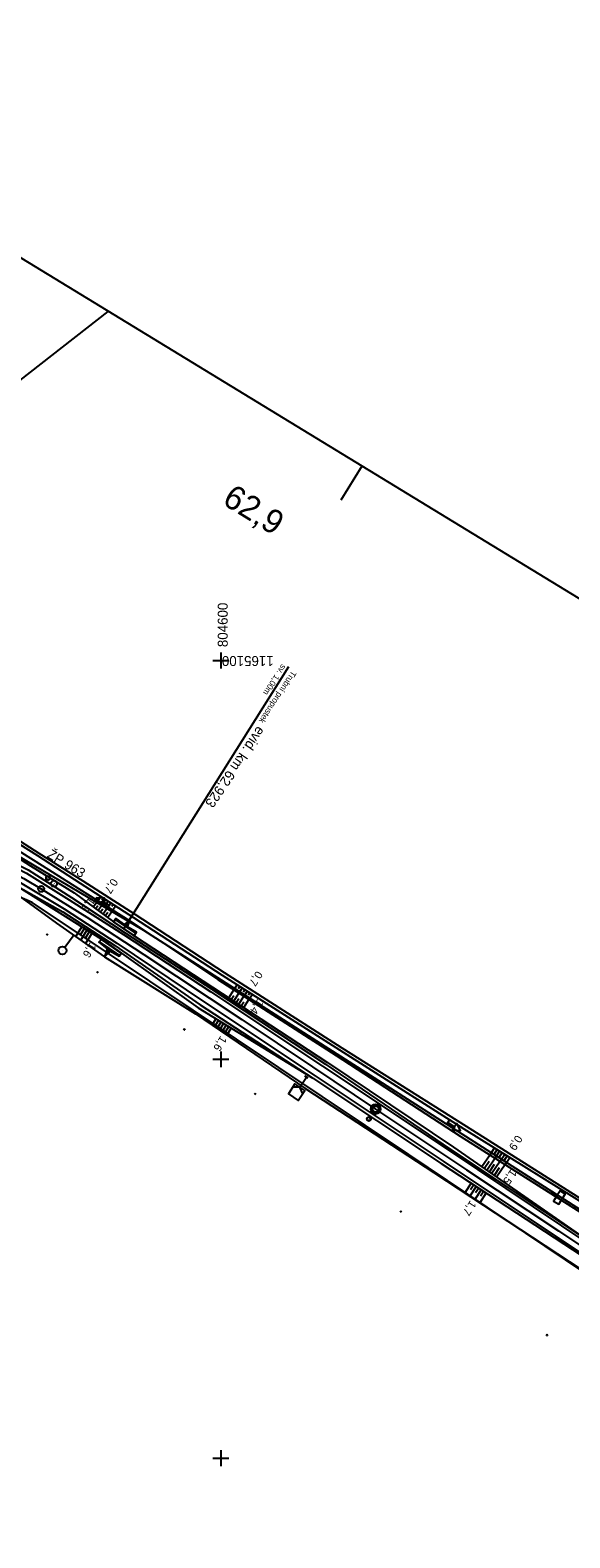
# Model space of a CAD drawing. Extents: x -804899 to -803847, y -1165742 to -1164942.
# Drawn here: x -804647.9 to -804512.4, y -1165320 to -1164941.9 of the extents above; entities that cross this region are included whole.
import ezdxf

# ---------------------------------------------------------------- set-up
doc = ezdxf.new("R2010")
doc.units = 0
for name, color, linetype in [('0381KM061-064P - Vrstva 1', 7, 'Continuous'), ('0381KM061-064P - Vrstva 17', 7, 'Continuous'), ('0381KM061-064P - Vrstva 19', 7, 'Continuous'), ('0381KM061-064P - Vrstva 36', 7, 'Continuous'), ('0381KM061-064P - Vrstva 4', 7, 'Continuous'), ('0381KM061-064P - Vrstva 48', 7, 'Continuous'), ('0381KM061-064P - Vrstva 49', 7, 'Continuous'), ('0381KM061-064P - Vrstva 51', 7, 'Continuous'), ('0381KM061-064P - Vrstva 55', 7, 'Continuous'), ('0381KM061-064P - Vrstva 7', 7, 'Continuous'), ('formát', 7, 'Continuous'), ('hran DP - hran DP', 7, 'Continuous'), ('krizky_1000 - souradnice', 7, 'Continuous'), ('krizky_1000 - Vrstva 1', 7, 'Continuous'), ('vyt_sit - stávající', 7, 'Continuous')]:
    doc.layers.add(name, color=color, linetype=linetype)

msp = doc.modelspace()

# ---------------------------------------------------------------- linework, layer by layer
at = {"layer": '0381KM061-064P - Vrstva 1'}
for points in [[(-804666.44, -1165145.5), (-804649.48, -1165154.65), (-804645.14, -1165157.27), (-804633.7, -1165164.38), (-804619.36, -1165173.74)], [(-804619.36, -1165173.74), (-804594.78, -1165190.05), (-804577, -1165201.91), (-804561.16, -1165212.47), (-804538.32, -1165227.67), (-804515.3, -1165243.02), (-804489.41, -1165260.27), (-804477.81, -1165268), (-804447.6, -1165288.14), (-804422.03, -1165305.2), (-804398.19, -1165321.09), (-804394.23, -1165323.73), (-804371.85, -1165338.65), (-804349.9, -1165353.29), (-804326.64, -1165368.8), (-804303.84, -1165384.01), (-804280.33, -1165399.7), (-804257.04, -1165415.23), (-804233.85, -1165430.69)]]:
    msp.add_lwpolyline(points, dxfattribs=at)
at = {"layer": '0381KM061-064P - Vrstva 17'}
for p, q in [((-804621.51, -1165168.31), (-804626.41, -1165164.99)), ((-804625.42, -1165173.99), (-804630.34, -1165170.65))]:
    msp.add_line(p, q, dxfattribs=at)
at = {"layer": '0381KM061-064P - Vrstva 19'}
msp.add_line((-804624.36, -1165167.24), (-804582.93, -1165101.49), dxfattribs=at)
for points in [[(-804626.92, -1165165.53), (-804626.96, -1165165.56), (-804626.42, -1165164.7), (-804626.38, -1165164.82)], [(-804621.79, -1165169), (-804626.96, -1165165.56)], [(-804621.8, -1165168.94), (-804626.92, -1165165.53), (-804626.38, -1165164.82), (-804621.37, -1165168.24), (-804621.8, -1165168.94)], [(-804626.42, -1165164.7), (-804624.29, -1165166.16)], [(-804621.2, -1165168.14), (-804623.43, -1165166.8)], [(-804630, -1165169.94), (-804629.95, -1165169.87), (-804630.64, -1165170.63), (-804630.54, -1165170.53)], [(-804630.64, -1165170.63), (-804628.58, -1165172.3)], [(-804630, -1165169.94), (-804630.54, -1165170.53), (-804625.53, -1165174.1), (-804625.05, -1165173.39), (-804630, -1165169.94)], [(-804629.95, -1165169.87), (-804624.97, -1165173.36)], [(-804621.8, -1165168.94), (-804621.79, -1165169), (-804621.2, -1165168.14), (-804621.37, -1165168.24)], [(-804625.53, -1165174.17), (-804627.74, -1165172.9)], [(-804625.05, -1165173.39), (-804624.97, -1165173.36), (-804625.53, -1165174.17), (-804625.53, -1165174.1)]]:
    msp.add_lwpolyline(points, dxfattribs=at)
for centre, major_axis, ratio, start_param, end_param in [((-804623.85, -1165166.5), (0.523, -0.388), 0.037903, 2.58802, 6.935719), ((-804623.82, -1165166.48), (-0.635, 0.468), 0.043076, 0.77347, 2.26914), ((-804628.16, -1165172.59), (-0.458, 0.324), 0.038427, 2.752706, 6.687548), ((-804628.11, -1165172.52), (0.511, -0.363), 0.262854, 3.749744, 5.691062)]:
    msp.add_ellipse(centre, major_axis=major_axis, ratio=ratio, start_param=start_param, end_param=end_param, dxfattribs=at)
at = {"layer": '0381KM061-064P - Vrstva 36'}
for p, q in [((-804639.21, -1165171.9), (-804636.83, -1165168.69)), ((-804639.81, -1165172.7), (-804639.81, -1165172.7))]:
    msp.add_line(p, q, dxfattribs=at)
msp.add_circle((-804639.81, -1165172.7), 1, dxfattribs=at)
at = {"layer": '0381KM061-064P - Vrstva 4'}
for points in [[(-804760.26, -1165118.8), (-804748.36, -1165120.01), (-804721.79, -1165126), (-804699.13, -1165133.38), (-804682.38, -1165139.58), (-804672.62, -1165144.09), (-804650.43, -1165155.7), (-804639.38, -1165162.29), (-804626.13, -1165170.89), (-804604.37, -1165185.52), (-804576.36, -1165204.15)], [(-804760.26, -1165118.8), (-804748.39, -1165120.75), (-804721.77, -1165126.98), (-804699.38, -1165134.38), (-804682.72, -1165140.57), (-804673.68, -1165144.67), (-804650.96, -1165156.64), (-804639.65, -1165163.02), (-804626.64, -1165171.43)], [(-804755.73, -1165115.93), (-804748.17, -1165116.91), (-804721.25, -1165123.25), (-804698.66, -1165130.22), (-804681.33, -1165136.99), (-804671.47, -1165141.65), (-804648.84, -1165153.36), (-804638.11, -1165160.03), (-804624.48, -1165168.7), (-804602.56, -1165183.07), (-804574.47, -1165201.72), (-804542.72, -1165222.84), (-804507.36, -1165246.55), (-804477.08, -1165266.82), (-804448.75, -1165285.88), (-804421.18, -1165304.15), (-804392.89, -1165323.09), (-804369.85, -1165338.37), (-804348.86, -1165352.04), (-804325.13, -1165367.98), (-804299.32, -1165385.27), (-804266.05, -1165407.31), (-804234.28, -1165428.6)], [(-804755.73, -1165115.93), (-804748.03, -1165116.49), (-804721.05, -1165122.36), (-804698.44, -1165129.77), (-804680.98, -1165136.5), (-804671.21, -1165140.89), (-804648.42, -1165152.46), (-804637.55, -1165159.43), (-804624.04, -1165168.29), (-804602.25, -1165182.38), (-804573.74, -1165201.2), (-804542.46, -1165222.56), (-804507.06, -1165246.03), (-804476.47, -1165266.24), (-804448.31, -1165285.08), (-804421.02, -1165303.1), (-804392.59, -1165322.59), (-804369.41, -1165337.65), (-804348.68, -1165351.59), (-804324.76, -1165367.42), (-804298.9, -1165384.42), (-804265.65, -1165406.5), (-804234.05, -1165428.04)], [(-804626.64, -1165171.43), (-804605.18, -1165186.34), (-804576.91, -1165204.69), (-804544.69, -1165226.09), (-804509.35, -1165249.3), (-804478.87, -1165269.77), (-804450.06, -1165288.98), (-804422.82, -1165307.11), (-804394.42, -1165325.66), (-804371.77, -1165341.24), (-804350.46, -1165355.38), (-804326.73, -1165371.34), (-804301.47, -1165388.34), (-804268.3, -1165410.72), (-804235.74, -1165432.01)], [(-804576.36, -1165204.15), (-804544.19, -1165225.52), (-804508.95, -1165249), (-804478.52, -1165269.18), (-804449.67, -1165288.56), (-804422.62, -1165306.58), (-804394.22, -1165325.33), (-804371.37, -1165340.61), (-804350.54, -1165354.66), (-804326.31, -1165370.81), (-804300.9, -1165387.72), (-804267.8, -1165409.92), (-804235.52, -1165431.44)]]:
    msp.add_lwpolyline(points, dxfattribs=at)
at = {"layer": '0381KM061-064P - Vrstva 48'}
for p, q in [((-804632.09, -1165161.79), (-804630.93, -1165160.22)), ((-804630.19, -1165159.11), (-804630.91, -1165160.23)), ((-804629.56, -1165159.52), (-804629.91, -1165160.07)), ((-804628.93, -1165159.92), (-804629.64, -1165161.03)), ((-804628.3, -1165160.33), (-804628.65, -1165160.88)), ((-804631.49, -1165162.24), (-804630.89, -1165161.43)), ((-804630.88, -1165162.68), (-804629.66, -1165161.02)), ((-804630.28, -1165163.12), (-804629.65, -1165162.27)), ((-804629.68, -1165163.57), (-804628.39, -1165161.82)), ((-804629.07, -1165164.01), (-804628.41, -1165163.12)), ((-804628.47, -1165164.46), (-804627.11, -1165162.62)), ((-804627.66, -1165160.74), (-804628.37, -1165161.83)), ((-804627.03, -1165161.14), (-804627.38, -1165161.69)), ((-804626.4, -1165161.55), (-804627.1, -1165162.63)), ((-804636.42, -1165169.21), (-804634.88, -1165166.77)), ((-804635.19, -1165170.08), (-804633.61, -1165167.56)), ((-804635.18, -1165168.65), (-804634.24, -1165167.17)), ((-804633.93, -1165169.49), (-804632.97, -1165167.97)), ((-804633.96, -1165170.94), (-804632.34, -1165168.36)), ((-804598.06, -1165184.55), (-804596.75, -1165182.56)), ((-804595.91, -1165181.26), (-804596.74, -1165182.56)), ((-804595.28, -1165181.67), (-804595.69, -1165182.32)), ((-804594.65, -1165182.07), (-804595.48, -1165183.37)), ((-804594.01, -1165182.47), (-804594.43, -1165183.13)), ((-804593.38, -1165182.88), (-804594.21, -1165184.19)), ((-804597.43, -1165184.97), (-804596.77, -1165183.97)), ((-804596.8, -1165185.38), (-804595.48, -1165183.37)), ((-804596.18, -1165185.79), (-804595.51, -1165184.78)), ((-804595.55, -1165186.2), (-804594.22, -1165184.18)), ((-804594.92, -1165186.61), (-804594.26, -1165185.6)), ((-804594.29, -1165187.02), (-804592.96, -1165184.99)), ((-804592.75, -1165183.28), (-804593.17, -1165183.94)), ((-804592.12, -1165183.68), (-804592.95, -1165185)), ((-804602.21, -1165191.42), (-804601.25, -1165189.83)), ((-804601.2, -1165191.2), (-804600.61, -1165190.23)), ((-804600.97, -1165192.26), (-804599.97, -1165190.62)), ((-804599.94, -1165192.01), (-804599.33, -1165191.01)), ((-804599.73, -1165193.11), (-804598.69, -1165191.4)), ((-804598.68, -1165192.83), (-804598.05, -1165191.79)), ((-804598.49, -1165193.95), (-804597.41, -1165192.18)), ((-804532.42, -1165223.96), (-804534.52, -1165226.99)), ((-804532.42, -1165223.97), (-804531.32, -1165222.2)), ((-804531.34, -1165223.66), (-804530.68, -1165222.6)), ((-804531.15, -1165224.77), (-804530.05, -1165223)), ((-804530.07, -1165224.46), (-804529.41, -1165223.39)), ((-804529.88, -1165225.57), (-804528.77, -1165223.79)), ((-804528.8, -1165225.26), (-804528.14, -1165224.18)), ((-804528.61, -1165226.37), (-804527.5, -1165224.58)), ((-804532.63, -1165225.59), (-804533.9, -1165227.42)), ((-804531.15, -1165224.77), (-804533.29, -1165227.85)), ((-804531.38, -1165226.41), (-804532.67, -1165228.27)), ((-804529.88, -1165225.57), (-804532.06, -1165228.7)), ((-804530.12, -1165227.23), (-804531.44, -1165229.13)), ((-804528.61, -1165226.37), (-804530.82, -1165229.55)), ((-804537.15, -1165231.04), (-804538.77, -1165233.51)), ((-804535.89, -1165231.86), (-804537.51, -1165234.33)), ((-804536.52, -1165231.45), (-804537.33, -1165232.69)), ((-804535.27, -1165232.28), (-804536.08, -1165233.51)), ((-804534.64, -1165232.69), (-804536.26, -1165235.15)), ((-804533.39, -1165233.51), (-804535.01, -1165235.98)), ((-804534.01, -1165233.1), (-804534.82, -1165234.33))]:
    msp.add_line(p, q, dxfattribs=at)
at = {"layer": '0381KM061-064P - Vrstva 49'}
for p, q in [((-804624.29, -1165166.16), (-804622.88, -1165165.28)), ((-804623.76, -1165166.56), (-804622.88, -1165165.28)), ((-804623.43, -1165166.8), (-804622.88, -1165165.28)), ((-804643.42, -1165168.96), (-804643.77, -1165168.6)), ((-804643.42, -1165168.6), (-804643.77, -1165168.96)), ((-804628.13, -1165172.71), (-804629.21, -1165174.28)), ((-804630.84, -1165178.37), (-804631.19, -1165178.02)), ((-804630.84, -1165178.02), (-804631.19, -1165178.37)), ((-804609.02, -1165192.71), (-804609.37, -1165192.36)), ((-804609.02, -1165192.36), (-804609.37, -1165192.71)), ((-804591.22, -1165208.93), (-804591.58, -1165208.57)), ((-804591.22, -1165208.57), (-804591.58, -1165208.93)), ((-804554.65, -1165238.41), (-804555.01, -1165238.06)), ((-804554.65, -1165238.06), (-804555.01, -1165238.41)), ((-804517.98, -1165269.33), (-804518.34, -1165268.98)), ((-804517.98, -1165268.98), (-804518.34, -1165269.33))]:
    msp.add_line(p, q, dxfattribs=at)
for points in [[(-804669.51, -1165137.6), (-804647.83, -1165151.5), (-804636.87, -1165158.28), (-804626.96, -1165165.56)], [(-804668.53, -1165136.56), (-804646.51, -1165150.38), (-804635.75, -1165157.19), (-804622.88, -1165165.28), (-804600.74, -1165180), (-804571.06, -1165199.05), (-804539.91, -1165219.23), (-804504.85, -1165241.38), (-804474.07, -1165260.59), (-804445.75, -1165278.86), (-804417.38, -1165297.08), (-804386.13, -1165316.29), (-804343.68, -1165343.22), (-804323.05, -1165356.81), (-804293.41, -1165375.48), (-804263.45, -1165394.43), (-804234.68, -1165412.78)], [(-804668.09, -1165135.13), (-804646.08, -1165148.91), (-804635.34, -1165155.79), (-804621.98, -1165164.4), (-804599.68, -1165178.86), (-804570.23, -1165197.63), (-804539.04, -1165217.4), (-804503.79, -1165239.32), (-804473.21, -1165259.25), (-804445.02, -1165277.37), (-804416.3, -1165295.6), (-804385.23, -1165314.87), (-804342.84, -1165342.16), (-804322.16, -1165355.5), (-804292.15, -1165374.6), (-804262.58, -1165393.44), (-804234.25, -1165411.43)], [(-804650.96, -1165156.64), (-804629.95, -1165169.87)], [(-804651.73, -1165158.22), (-804641.24, -1165165.82), (-804629.21, -1165174.28), (-804606.38, -1165188.59), (-804578.69, -1165207.38), (-804546.55, -1165228.41), (-804509.4, -1165252.77), (-804482.02, -1165272.35), (-804454.07, -1165289.87), (-804424.02, -1165310.32)], [(-804624.29, -1165166.16), (-804626.42, -1165164.7), (-804626.96, -1165165.56)], [(-804621.79, -1165169), (-804621.2, -1165168.14), (-804623.43, -1165166.8)], [(-804629.95, -1165169.87), (-804630.64, -1165170.63), (-804628.58, -1165172.3)], [(-804621.79, -1165169), (-804602.1, -1165181.9), (-804573.29, -1165200.8), (-804541.65, -1165222.05), (-804507.06, -1165246.03), (-804476.55, -1165265.48), (-804448.31, -1165285.08)], [(-804628.58, -1165172.3), (-804629.21, -1165174.28), (-804627.74, -1165172.9)], [(-804627.74, -1165172.9), (-804625.53, -1165174.17), (-804624.97, -1165173.36)], [(-804624.97, -1165173.36), (-804605.7, -1165187.12), (-804576.91, -1165204.69)], [(-804576.91, -1165204.69), (-804544.69, -1165226.09), (-804509.35, -1165249.3), (-804478.87, -1165269.77), (-804450.06, -1165288.98), (-804422.82, -1165307.11), (-804394.42, -1165325.66), (-804371.77, -1165341.24), (-804350.46, -1165355.38), (-804326.73, -1165371.34), (-804301.47, -1165388.34), (-804268.3, -1165410.72), (-804235.74, -1165432.01)]]:
    msp.add_lwpolyline(points, dxfattribs=at)
for centre, major_axis, ratio, start_param, end_param in [((-804623.82, -1165166.48), (0.635, -0.468), 0.043076, 3.915063, 5.410733), ((-804628.11, -1165172.52), (-0.511, 0.363), 0.262854, 0.608151, 2.549469)]:
    msp.add_ellipse(centre, major_axis=major_axis, ratio=ratio, start_param=start_param, end_param=end_param, dxfattribs=at)
at = {"layer": '0381KM061-064P - Vrstva 51'}
for p, q in [((-804628.33, -1165161.87), (-804627.81, -1165161.01)), ((-804542.75, -1165215.4), (-804543.3, -1165216.24)), ((-804516.68, -1165233.05), (-804517.22, -1165233.9))]:
    msp.add_line(p, q, dxfattribs=at)
for points in [[(-804728.9, -1165105.9), (-804711.54, -1165108.67), (-804704.35, -1165111.8), (-804683.69, -1165124.09), (-804676.95, -1165128.43), (-804667.36, -1165134.41), (-804645.71, -1165148.3), (-804634.7, -1165155.23), (-804621.63, -1165163.62), (-804599.19, -1165178.23), (-804569.67, -1165197.16), (-804538.42, -1165216.77), (-804503.41, -1165238.94), (-804472.82, -1165258.55), (-804444.57, -1165276.4), (-804415.82, -1165294.73), (-804384.7, -1165314.57), (-804342.59, -1165341.72), (-804321.8, -1165355.02), (-804291.77, -1165374.22), (-804262.45, -1165392.96)], [(-804628.07, -1165161.44), (-804629.78, -1165160.4), (-804629.26, -1165159.55), (-804631.28, -1165159.49), (-804630.3, -1165161.26), (-804629.78, -1165160.4)], [(-804543.03, -1165215.82), (-804541.36, -1165216.93), (-804541.91, -1165217.76), (-804539.9, -1165217.89), (-804540.81, -1165216.09), (-804541.36, -1165216.93)], [(-804516.95, -1165233.47), (-804515.68, -1165234.27), (-804516.48, -1165235.54), (-804515.21, -1165236.34), (-804513.61, -1165233.8), (-804514.88, -1165233), (-804515.68, -1165234.27)]]:
    msp.add_lwpolyline(points, dxfattribs=at)
at = {"layer": '0381KM061-064P - Vrstva 55'}
msp.add_lwpolyline([(-804834.02, -1165173.21), (-804777.95, -1165165.95), (-804761.65, -1165133.49), (-804755.48, -1165121.19), (-804751.26, -1165114.04), (-804741.92, -1165100.8), (-804736.13, -1165096.49), (-804701.79, -1165069.72), (-804628.3, -1165012.44)], dxfattribs=at)
at = {"layer": '0381KM061-064P - Vrstva 7'}
for p, q in [((-804643.44, -1165154.52), (-804643.36, -1165154.57)), ((-804580.17, -1165206.99), (-804578.52, -1165204.48)), ((-804578.1, -1165204.76), (-804578.93, -1165204.21)), ((-804562.9, -1165214.95), (-804562.82, -1165215.01))]:
    msp.add_line(p, q, dxfattribs=at)
for points in [[(-804580.17, -1165206.99), (-804581.42, -1165206.16), (-804583.08, -1165208.66), (-804580.58, -1165210.32), (-804578.92, -1165207.81), (-804580.17, -1165206.99)], [(-804579.47, -1165208.65), (-804580.17, -1165206.99), (-804581.98, -1165206.99)]]:
    msp.add_lwpolyline(points, dxfattribs=at)
for centre, radius in [((-804645.14, -1165157.27), 0.75), ((-804643.4, -1165154.55), 0.5), ((-804561.16, -1165212.47), 1.25), ((-804561.16, -1165212.47), 0.752), ((-804562.86, -1165214.98), 0.5)]:
    msp.add_circle(centre, radius, dxfattribs=at)
at = {"layer": 'formát'}
for p, q in [((-804206.05, -1165269.84), (-804743.98, -1164941.92)), ((-804564.67, -1165051.23), (-804569.87, -1165059.77))]:
    msp.add_line(p, q, dxfattribs=at)
at = {"layer": 'hran DP - hran DP'}
for p, q in [((-804647.39, -1165160.7), (-804728.07, -1165125.68)), ((-804680.02, -1165131.72), (-804619.47, -1165167.61)), ((-804628.74, -1165173.15), (-804647.39, -1165160.7)), ((-804619.47, -1165167.61), (-804573.03, -1165197.25)), ((-804552.85, -1165223.84), (-804628.74, -1165173.15)), ((-804573.03, -1165197.25), (-804519.76, -1165231.32)), ((-804418.46, -1165314.18), (-804552.85, -1165223.84)), ((-804519.76, -1165231.32), (-804468.27, -1165264.32))]:
    msp.add_line(p, q, dxfattribs=at)
at = {"layer": 'krizky_1000 - Vrstva 1'}
for points in [[(-804600, -1165098), (-804600, -1165102)], [(-804602, -1165100), (-804598, -1165100)], [(-804600, -1165198), (-804600, -1165202)], [(-804602, -1165200), (-804598, -1165200)], [(-804602, -1165300), (-804598, -1165300)], [(-804600, -1165298), (-804600, -1165302)]]:
    msp.add_lwpolyline(points, dxfattribs=at)
at = {"layer": 'vyt_sit - stávající'}
msp.add_line((-804641.97, -1165155.91), (-804641.88, -1165155.96), dxfattribs=at)
msp.add_circle((-804641.93, -1165155.93), 0.756, dxfattribs=at)

# ---------------------------------------------------------------- texts
at = {"layer": '0381KM061-064P - Vrstva 19'}
for s, height, rotation, p in [('Trubní propustek', 1.5, 236.6035, (-804582.22, -1165102.45)), ('sv. 1,00m', 1.5, 236.6035, (-804584.72, -1165100.8)), ('evid. km 62,923', 2.5, 235.6365, (-804590.77, -1165116.28))]:
    msp.add_text(s, height=height, rotation=rotation, dxfattribs=at).set_placement(p)
at = {"layer": '0381KM061-064P - Vrstva 48'}
for s, rotation, p in [('0,7', 237.184, (-804627.36, -1165154.47)), ('1,2', 233.6713, (-804633.01, -1165159.16)), ('1,6', 237.8043, (-804632.81, -1165170.52)), ('0,7', 237.4892, (-804591.05, -1165177.68)), ('1,4', 236.7324, (-804590.78, -1165184.72)), ('1,6', 238.5896, (-804600.07, -1165193.98)), ('0,9', 238.1314, (-804525.86, -1165218.85)), ('1,5', 235.2728, (-804527.19, -1165227.42)), ('1,7', 236.7061, (-804537.39, -1165235.24))]:
    msp.add_text(s, height=2, rotation=rotation, dxfattribs=at).set_placement(p)
at = {"layer": '0381KM061-064P - Vrstva 7'}
msp.add_text('62,9', height=6, rotation=328.3791, dxfattribs=at).set_placement((-804599.94, -1165060.6))
at = {"layer": 'krizky_1000 - souradnice'}
for s, rotation, p in [('804600', 90, (-804598.3, -1165096.64)), ('1165100', 180, (-804586.75, -1165098.87))]:
    msp.add_text(s, height=2.5, rotation=rotation, dxfattribs=at).set_placement(p)
at = {"layer": 'vyt_sit - stávající'}
msp.add_text('ŽP 963', height=2.4, rotation=328.5611, dxfattribs=at).set_placement((-804643.81, -1165149.22))

doc.saveas('drawing.dxf')
